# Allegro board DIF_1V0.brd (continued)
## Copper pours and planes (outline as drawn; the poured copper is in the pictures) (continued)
3.3V_OUT on TOP (solid shape): 23.16,65.23 22.53,65.23 22.53,64.24 22.5,64.24 22.5,63.42 22.02,63.42 22.02,62.03 20.02,62.03 20.02,61.42 19.13,61.42 19.13,62.69 19.68,62.69 19.68,62.71 20.19,62.71 20.19,63.65 20.27,63.65 20.27,65.94 21.21,65.94 21.21,68.12 23.16,68.12
3.3V_OUT_DET on TOP: 1.24,79.63 1.24,86.33 4.57,86.33 4.57,83.69 7.29,83.69 7.29,79.63
3.3V_OUT_DET on PLANE3: 1.52,79.65 1.52,100.08 150.88,100.08 150.88,87.93 128.52,87.93 128.52,96.65 18.47,96.65 13.51,91.69 13.51,88.29 8,88.29 8,79.65
5.0V_HV on TOP: 2.03,77.52 2.03,73.74 10.03,73.74 10.03,77.52
5.0V_HV on TOP: 0.81,67.74 0.81,57.48 3.66,57.48 3.66,67.74
5.0V_HV on BOTTOM: 0.69,69.75 0.69,64.16 6.17,64.16 6.17,69.75
5.0V_HV on BOTTOM: 0.69,61.59 0.69,56.97 5.44,56.97 5.44,61.59
5.0V_HV on PLANE3: 1.52,56.82 1.52,79.15 8.51,79.15 8.51,87.43 13.51,87.43 13.51,86.41 52.81,86.41 52.81,89.33 57.78,89.33 57.78,80.06 17.22,80.06 17.22,56.82
+5VIN on TOP: 2.51,36.14 2.51,43.61 12.19,43.61 12.19,41.94 17.81,41.94 17.81,36.14
+5VIN on BOTTOM: 8.71,34.21 8.71,39.19 3.15,39.19 3.15,43.84 17.86,43.84 17.86,34.21
+5VIN on PLANE3: 1.52,34.49 1.52,56.31 17.22,56.31 17.22,34.49
VCC5V0 on TOP: 18.52,58.72 18.52,55.45 25.27,55.45 25.27,58.72
VCC5V0 on TOP: 20.37,39.85 20.37,36.2 27.99,36.2 27.99,39.85
VCC5V0 on TOP: 13.39,24.99 13.39,28.75 16.84,28.75 16.84,27.36 20.27,27.36 20.27,27.76 24.89,27.76 24.89,25.07 16.84,25.07 16.84,24.99
VCC5V0 on TOP: 9.58,11.96 9.58,12.04 8.59,12.04 8.59,16 10.82,16 10.82,14.35 15.65,14.35 15.65,11.96
VCC5V0 on TOP: 12.12,49.94 12.12,43.66 19.05,43.66 19.05,49.94
VCC5V0 on PLANE5: 1.52,10.67 1.52,60.48 30.18,60.48 30.18,27.05 23.8,27.05 23.8,16.28 30.18,16.28 30.18,10.67
0 on TOP: 37.82,29.74 37.82,27.64 35.66,27.64 35.66,29.74
0 on TOP: 48.59,28.4 48.59,26.06 54,26.06 54,28.4
0 on TOP: 95.86,34.67 95.86,28.57 92.15,28.57 92.15,34.67
0 on TOP: 0.86,0.61 0.86,50.72 1.07,50.72 1.07,50.75 5,50.75 5,57.68 6.35,57.68 6.35,57.58 6.71,57.58 6.71,59.33 6.55,59.33 6.55,60.2 3.89,60.2 3.89,60.48 6.4,60.48 6.4,68.25 3.89,68.25 3.89,68.81 0.86,68.81 0.86,73.1 9.93,73.1 10.03,73.2 10.06,73.2 10.06,73.23 10.16,73.33 10.16,87.68 9.8,88.04 0.99,88.04 0.86,87.91 0.86,97.23 4.57,97.23 4.57,100.79 148.13,100.79 148.13,98.98 150.72,98.98 150.72,0.61 ; 13 cut-outs
0 on TOP: 64.9,16.92 64.9,13.03 71.78,13.03 71.78,16.92
0 on TOP: 82.22,96.52 82.22,94.77 133.91,94.77 133.91,96.52
0 on TOP: 73.1,25.96 73.1,22.76 74.9,22.76 74.9,25.96
0 on BOTTOM: 0.66,0.76 0.66,56.72 5.94,56.72 5.94,62.1 0.66,62.1 0.66,63.98 6.32,63.98 6.32,70.79 0.66,70.79 0.66,101.04 151.59,101.04 151.59,0.76 ; 17 cut-outs
0 on BOTTOM: 87.05,37.97 87.05,38.96 86.56,38.96 86.56,40.64 87.1,40.64 88.27,39.47 88.27,37.97
0 on PLANE3: 1.52,1.52 1.52,33.99 106.1,33.99 106.1,67.39 74.04,67.39 74.04,49.1 17.73,49.1 17.73,79.55 58.29,79.55 58.29,89.84 52.3,89.84 52.3,86.92 14.02,86.92 14.02,91.49 18.67,96.14 128.02,96.14 128.02,87.43 150.42,87.43 150.42,67.46 150.88,67.46 150.88,1.52
0 on GND4, GND6: 151.38,1.02 1.02,1.02 1.02,100.58 151.38,100.58
0 on PLANE5: 1.52,100.08 1.52,74.09 150.88,74.09 150.88,100.08
0 on PLANE7: 17.7,1.52 17.7,24.21 58.98,24.21 58.98,24.87 79.2,24.87 79.2,24.21 107.14,24.21 107.14,71.37 123.9,71.37 123.9,90.42 119.02,90.42 119.02,77.01 22.61,77.01 22.61,71.88 1.52,71.88 1.52,100.08 150.88,100.08 150.88,1.52
N64906 on PLANE7: 119.53,89.92 123.39,89.92 123.39,71.88 23.11,71.88 23.11,76.5 119.53,76.5

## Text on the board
Ref Des/Silkscreen Bottom: HV_CAP | 1 | JTAG | SLWR | CLK_50M | P | CK_40 | 24LC64 | TRIG | N | ADM706 | Reset Chip | XO75L GTPCLK
Ref Des/Silkscreen Top: 3.3_DET | 1 | VIN | GND | + | +5V | 1.2V | 1.0V | 3.3V | DA3 | DA2 | 5V | LVDS31 | HV | DA4 | HV CAP | DA6 | LVDS32 | 14 | 0 | DA1 | DA5 | USB CFIG | SLOE | FLC | 30 | N25Q128 | RESET USB | CK_5M | RESET FPGA | PROGRAM B | GND 0 | M2
DIMENSION: Differential Pairs
